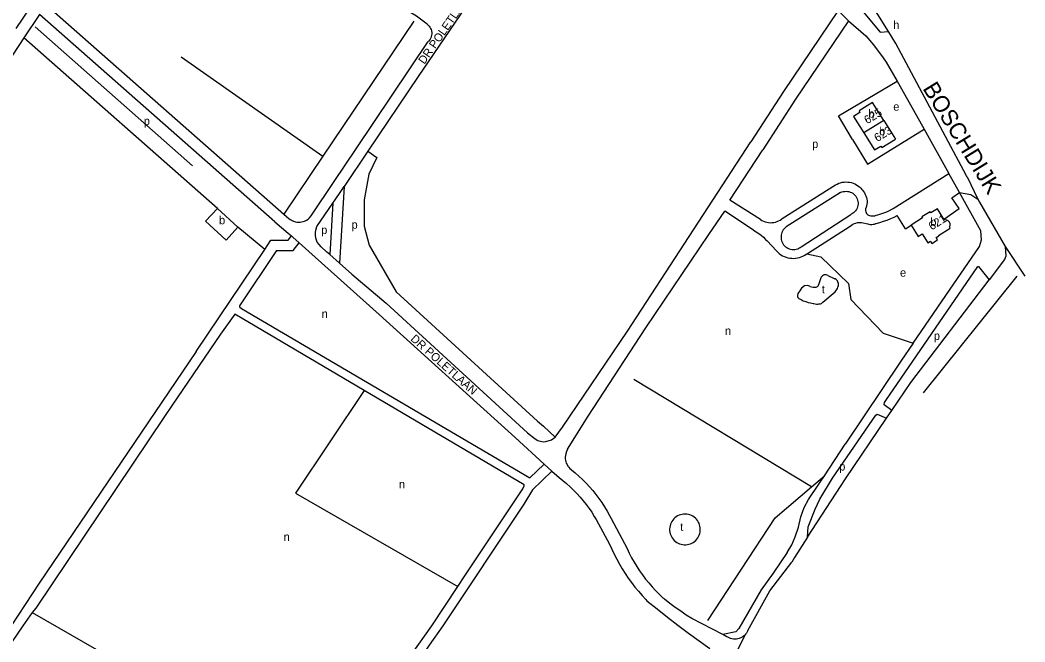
# Model space of a CAD drawing. Extents: x 158142 to 159655, y 385262 to 387204.
# Drawn here: x 159167.3 to 159654.9, y 385692.2 to 385994 of the extents above; entities that cross this region are included whole.
import ezdxf

# ---------------------------------------------------------------- set-up
doc = ezdxf.new("R2010")
doc.units = 0
for name, color, linetype in [('BLT_Basislijn', 7, 'Continuous'), ('BLT_Bebouwing', 7, 'Continuous'), ('BLT_Centroide', 7, 'Continuous'), ('BLT_Huisnummer', 7, 'Continuous'), ('BLT_Onderverdeling_panden', 7, 'Continuous'), ('BLT_Straatnaam_hoofdweg', 7, 'Continuous'), ('BLT_Straatnaam_verkleind', 7, 'Continuous'), ('BLT_Vlakafsluiter', 7, 'Continuous')]:
    doc.layers.add(name, color=color, linetype=linetype)

msp = doc.modelspace()

# ---------------------------------------------------------------- linework, layer by layer
at = {"layer": 'BLT_Basislijn'}
for p, q in [((159165.42, 385989.96), (159172.45, 386000.38)), ((159179.88, 386001.36), (159295.25, 385899.78)), ((159383.2, 386000), (159360.49, 385966.58)), ((159290.95, 385896.13), (159176.74, 385996.68)), ((159569.35, 385993.56), (159564.29, 385998.58)), ((159250.97, 385923.21), (159174.53, 385990.69)), ((159358.31, 385993.36), (159314.24, 385927.96)), ((159263.05, 385902.6), (159169.11, 385985.31)), ((159245.48, 385976.08), (159314.24, 385927.96)), ((159360.49, 385966.58), (159336.02, 385930.3)), ((159578.44, 385923.99), (159605.99, 385941.01)), ((159605.99, 385941.01), (159617.99, 385919.5)), ((159314.24, 385927.96), (159295.25, 385899.78)), ((159336.02, 385930.3), (159324.47, 385913.16)), ((159590.91, 385902.54), (159617.99, 385919.5)), ((159623.13, 385910.29), (159617.99, 385919.5)), ((159322.2, 385909.83), (159324.47, 385913.16)), ((159324.47, 385913.16), (159322.29, 385876.01)), ((159537.1, 385897.66), (159562.94, 385914)), ((159318.98, 385905.1), (159322.2, 385909.83)), ((159565.46, 385910.29), (159539.08, 385893.57)), ((159311.3, 385893.79), (159318.98, 385905.1)), ((159318.98, 385905.1), (159317.52, 385880.19)), ((159526.56, 385897.16), (159511.75, 385906.61)), ((159295.25, 385899.78), (159296.58, 385898.66)), ((159501.52, 385889.86), (159509.26, 385901.2)), ((159523.24, 385892.05), (159509.26, 385901.2)), ((159546.3, 385883.94), (159570.38, 385899.66)), ((159596.86, 385892.71), (159592.94, 385899.15)), ((159285.98, 385882.6), (159272.98, 385893.46)), ((159575.57, 385895.82), (159578.58, 385895.15)), ((159596.86, 385892.71), (159599.63, 385894.4)), ((159529.74, 385886.79), (159534.26, 385881.93)), ((159322.29, 385876.01), (159317.52, 385880.19)), ((159555.71, 385868.37), (159554.77, 385865.49)), ((159559.26, 385870.08), (159562.65, 385868.45)), ((159605.69, 385813.08), (159651.1, 385869.64)), ((159550.72, 385864.76), (159549.53, 385865.12)), ((159564.26, 385866.46), (159564.33, 385865.81)), ((159556.84, 385857.08), (159562.73, 385862.17)), ((159600.69, 385837.12), (159616.57, 385860.29)), ((159551.36, 385767.53), (159465.1, 385819.54)), ((159587.74, 385800.74), (159590.24, 385804.58)), ((159407.5, 385791.35), (159421.66, 385778.49)), ((159557.56, 385772.84), (159567.69, 385788.19)), ((159414.68, 385771.79), (159421.66, 385778.49)), ((159421.66, 385778.49), (159425.37, 385775.12)), ((159415.91, 385766.04), (159425.37, 385775.12)), ((159425.37, 385775.12), (159428.86, 385771.95)), ((159551.36, 385767.53), (159557.56, 385772.84)), ((159446.83, 385751.56), (159453.35, 385739.65)), ((159454.18, 385752.06), (159461.79, 385737.52)), ((159173.19, 385706.41), (159315.87, 385624.7)), ((159508.31, 385695.75), (159493.3, 385703.52)), ((159510.31, 385694.72), (159508.31, 385695.75))]:
    msp.add_line(p, q, dxfattribs=at)
for points in [[(159588.66, 385988.41), (159476.89, 386166.67), (159406.2, 386279.27)], [(159478.02, 386149.53), (159562.65, 386014.57), (159584.59, 385988.03), (159588.66, 385988.41)], [(159364.77, 385991.98), (159359.67, 385995.81), (159357.27, 385997.38), (159341.92, 386007.64), (159333.04, 386014.11), (159326.2, 386021.62)], [(159176.74, 385996.68), (159169.11, 385985.31)], [(159564.29, 385998.58), (159537.79, 385959.39), (159521.82, 385934.86)], [(159364.77, 385991.98), (159365.28, 385991.55), (159365.74, 385991.06), (159366.13, 385990.52), (159366.46, 385989.94), (159366.72, 385989.32), (159366.9, 385988.68), (159367, 385988.01), (159367.02, 385987.34), (159366.97, 385986.68), (159366.83, 385986.02), (159366.62, 385985.39), (159366.33, 385984.78), (159365.97, 385984.22), (159365.55, 385983.7), (159365.36, 385983.5)], [(159569.35, 385993.56), (159543.62, 385955.52), (159527.68, 385931.04)], [(159569.35, 385993.56), (159577.76, 385986.31), (159581.37, 385981.9), (159586.11, 385975.62)], [(159169.11, 385985.31), (159163.85, 385977.46), (159080.85, 385855.39)], [(159626.86, 385917.98), (159626.6, 385918.4), (159592.32, 385982.55), (159588.66, 385988.41)], [(159330.32, 385931.44), (159365.36, 385983.5)], [(159586.11, 385975.62), (159587.63, 385973.6), (159592.87, 385964.31)], [(159571.26, 385935.96), (159564.45, 385947.48), (159592.87, 385964.31)], [(159592.87, 385964.31), (159603.72, 385945.1), (159605.99, 385941.01)], [(159426.86, 385791.61), (159430.45, 385796.38), (159461.95, 385843.05), (159521.82, 385934.86)], [(159571.26, 385935.96), (159578.44, 385923.99)], [(159308.47, 385898.93), (159319.67, 385915.57), (159330.32, 385931.44)], [(159336.02, 385930.3), (159340.38, 385927.36), (159336.47, 385919.19), (159334.27, 385906.66), (159334.27, 385893.95), (159336.63, 385884.7), (159349.77, 385862.08), (159418.41, 385799.31), (159421.34, 385796.91), (159426.86, 385791.61)], [(159511.75, 385906.61), (159527.68, 385931.04)], [(159562.94, 385914), (159563.73, 385914.42), (159564.54, 385914.78), (159565.39, 385915.05), (159566.26, 385915.26), (159567.14, 385915.38), (159568.03, 385915.42), (159568.92, 385915.39), (159569.8, 385915.27), (159570.67, 385915.08), (159571.52, 385914.8), (159572.34, 385914.46), (159573.13, 385914.04), (159573.87, 385913.55), (159574.57, 385913), (159575.22, 385912.38), (159575.81, 385911.71), (159576.07, 385911.37)], [(159565.46, 385910.29), (159566.09, 385910.56), (159566.74, 385910.75), (159567.42, 385910.86), (159568.1, 385910.9), (159568.79, 385910.86), (159569.46, 385910.73), (159570.11, 385910.53), (159570.74, 385910.25), (159571.33, 385909.91), (159571.87, 385909.49), (159572.37, 385909.02), (159572.8, 385908.49), (159573.17, 385907.91), (159573.47, 385907.3), (159573.7, 385906.65), (159573.85, 385905.99), (159573.92, 385905.3), (159573.91, 385904.62), (159573.82, 385903.94), (159573.65, 385903.28), (159573.41, 385902.64), (159573.09, 385902.03), (159572.7, 385901.47), (159572.26, 385900.95), (159571.75, 385900.49), (159571.19, 385900.09), (159570.6, 385899.76), (159570.38, 385899.66)], [(159576.07, 385911.37), (159576.59, 385910.75), (159577.05, 385910.08), (159577.44, 385909.36), (159577.76, 385908.61), (159578, 385907.84), (159578.17, 385907.04), (159578.26, 385906.23), (159578.26, 385905.42), (159578.19, 385904.61), (159578.04, 385903.81), (159577.81, 385903.03), (159577.74, 385902.84)], [(159615.82, 385897.53), (159623, 385902.5), (159619.42, 385907.77), (159623.13, 385910.29)], [(159616.57, 385860.29), (159632.84, 385884.02), (159633.89, 385887.25), (159633.44, 385891.67), (159623.13, 385910.29)], [(159623.13, 385910.29), (159628.68, 385909.27), (159632, 385907.12)], [(159577.74, 385902.84), (159577.59, 385902.4), (159577.52, 385901.94), (159577.52, 385901.48), (159577.61, 385901.02), (159577.77, 385900.59), (159578.01, 385900.18), (159578.31, 385899.83), (159578.66, 385899.53), (159579.06, 385899.3), (159579.41, 385899.16)], [(159583.43, 385899.5), (159584.91, 385899.92), (159586.37, 385900.41), (159587.8, 385900.99), (159589.2, 385901.63), (159590.56, 385902.35), (159590.91, 385902.54)], [(159632, 385907.12), (159632.9, 385905.53), (159645.37, 385884.04)], [(159296.58, 385898.66), (159297.66, 385897.75), (159298.29, 385897.26), (159298.74, 385896.96), (159299.27, 385896.66), (159300, 385896.32), (159300.89, 385896.05), (159301.6, 385895.94), (159302.35, 385895.86), (159303.1, 385895.91), (159303.78, 385895.99), (159304.56, 385896.16), (159305.28, 385896.4), (159306.21, 385896.85), (159307, 385897.38), (159307.74, 385898.01), (159308.47, 385898.93)], [(159526.56, 385897.16), (159527.28, 385896.72), (159528.04, 385896.35), (159528.82, 385896.06), (159529.64, 385895.85), (159530.46, 385895.71), (159531.3, 385895.65), (159532.14, 385895.67), (159532.97, 385895.77), (159533.79, 385895.95), (159534.59, 385896.21), (159535.36, 385896.54), (159536.1, 385896.94), (159536.79, 385897.42), (159537.1, 385897.66)], [(159579.41, 385899.16), (159580.07, 385899.02), (159580.74, 385898.95), (159581.42, 385898.96), (159582.08, 385899.05), (159582.73, 385899.22), (159583.43, 385899.5)], [(159582.76, 385895.32), (159584.55, 385895.78), (159586.33, 385896.33), (159588.07, 385896.95), (159589.79, 385897.64), (159591.48, 385898.41), (159592.94, 385899.15)], [(159290.95, 385896.13), (159297.4, 385890.55)], [(159317.52, 385880.19), (159315.95, 385881.57), (159313.33, 385883.88), (159311.47, 385886.26), (159311.17, 385887.17), (159310.84, 385888.28), (159310.69, 385889.43), (159310.69, 385890.96), (159310.84, 385892.1), (159311.3, 385893.79)], [(159539.08, 385893.57), (159538.54, 385893.14), (159538.04, 385892.65), (159537.61, 385892.11), (159537.25, 385891.52), (159536.95, 385890.89), (159536.73, 385890.23), (159536.59, 385889.55), (159536.52, 385888.86), (159536.54, 385888.17), (159536.63, 385887.48), (159536.8, 385886.81), (159537.05, 385886.16), (159537.37, 385885.55), (159537.76, 385884.97), (159538.22, 385884.45), (159538.73, 385883.98), (159539.29, 385883.57), (159539.89, 385883.23), (159540.53, 385882.97), (159541.2, 385882.77), (159541.88, 385882.66), (159542.58, 385882.62), (159543.27, 385882.67), (159543.95, 385882.79), (159544.62, 385882.99), (159545.25, 385883.27), (159545.85, 385883.62), (159546.3, 385883.94)], [(159549.04, 385880.57), (159549.31, 385880.77), (159570.05, 385893.98)], [(159570.05, 385893.98), (159570.7, 385894.46), (159571.4, 385894.87), (159572.13, 385895.21), (159572.89, 385895.48), (159573.68, 385895.68), (159574.48, 385895.79), (159575.29, 385895.82), (159575.57, 385895.82)], [(159578.58, 385895.15), (159579.21, 385894.96), (159579.86, 385894.85), (159580.52, 385894.81), (159581.19, 385894.86), (159581.84, 385894.99), (159582.47, 385895.19), (159582.76, 385895.32)], [(159289.02, 385887.11), (159297.36, 385887.11), (159298.94, 385889.22)], [(159297.4, 385890.55), (159298.94, 385889.22)], [(159298.94, 385889.22), (159299.56, 385888.68), (159302.69, 385885.88)], [(159432.86, 385785.82), (159442.9, 385801.72), (159470.99, 385844.68), (159501.52, 385889.86)], [(159523.24, 385892.05), (159524.49, 385891.28), (159525.7, 385890.44), (159526.86, 385889.54), (159527.97, 385888.57), (159529.03, 385887.54), (159529.74, 385886.79)], [(159285.98, 385882.6), (159289.02, 385887.11)], [(159291.73, 385882.11), (159299.86, 385882.11), (159302.69, 385885.88)], [(159302.69, 385885.88), (159341.52, 385851.11)], [(159645.37, 385884.04), (159645.69, 385879.42), (159644.91, 385877.78), (159637.55, 385867.9)], [(159252.71, 385833.22), (159285.98, 385882.6)], [(159291.73, 385882.11), (159273.76, 385855.34), (159273.79, 385854.89), (159274.77, 385853.97), (159414.68, 385771.79)], [(159534.26, 385881.93), (159534.92, 385881.27), (159535.64, 385880.66), (159536.41, 385880.12), (159537.22, 385879.64), (159538.07, 385879.24), (159538.95, 385878.91), (159539.85, 385878.65), (159540.77, 385878.47), (159541.71, 385878.37), (159542.65, 385878.35), (159543.59, 385878.41), (159544.52, 385878.55), (159545.43, 385878.77), (159546.33, 385879.07), (159547.19, 385879.43), (159548.02, 385879.88), (159548.81, 385880.39), (159549.04, 385880.57)], [(159549.04, 385880.57), (159555.88, 385879.15), (159569.32, 385866.12), (159570.36, 385858.43), (159586.15, 385842.09), (159600.69, 385837.12)], [(159328.32, 385870.72), (159322.29, 385876.01)], [(159590.24, 385804.58), (159586.64, 385807.23), (159586.8, 385808.32), (159587.37, 385809.43), (159632.01, 385874.35), (159632.42, 385874.43), (159637.55, 385867.9)], [(159328.32, 385870.72), (159344.87, 385856.55), (159413.57, 385793.72), (159417.21, 385790.74), (159418.59, 385789.96), (159421.07, 385789.38), (159422.44, 385789.45), (159425.2, 385790.34), (159426.86, 385791.61)], [(159559.26, 385870.08), (159558.85, 385870.25), (159558.41, 385870.33), (159557.96, 385870.34), (159557.52, 385870.27), (159557.1, 385870.12), (159556.72, 385869.9), (159556.38, 385869.61), (159556.09, 385869.27), (159555.87, 385868.88), (159555.71, 385868.37)], [(159564.26, 385866.46), (159564.1, 385866.93), (159563.87, 385867.36), (159563.57, 385867.76), (159563.21, 385868.1), (159562.8, 385868.37), (159562.65, 385868.45)], [(159546.46, 385863.94), (159545.59, 385862.64), (159544.72, 385861.34), (159544.46, 385860.14)], [(159549.53, 385865.12), (159547.94, 385864.94), (159546.46, 385863.94)], [(159550.72, 385864.76), (159551.38, 385864.55), (159552.06, 385864.41), (159552.75, 385864.35), (159553.2, 385864.35)], [(159553.2, 385864.35), (159553.55, 385864.38), (159553.89, 385864.49), (159554.2, 385864.67), (159554.46, 385864.91), (159554.65, 385865.21), (159554.77, 385865.49)], [(159562.73, 385862.17), (159563.18, 385862.65), (159563.56, 385863.18), (159563.88, 385863.75), (159564.12, 385864.36), (159564.25, 385864.81)], [(159564.33, 385865.81), (159564.32, 385865.26), (159564.25, 385864.81)], [(159590.24, 385804.58), (159599.56, 385818.02), (159637.55, 385867.9)], [(159544.46, 385860.14), (159544.56, 385859.76), (159544.73, 385859.39), (159544.97, 385859.07), (159545.17, 385858.88)], [(159545.17, 385858.88), (159546.24, 385858.3), (159547.35, 385857.78), (159548.49, 385857.34), (159549.66, 385856.97), (159550.85, 385856.68), (159552.05, 385856.47), (159552.49, 385856.41)], [(159552.49, 385856.41), (159553.13, 385856.25), (159553.79, 385856.17), (159554.45, 385856.17), (159554.83, 385856.2)], [(159554.83, 385856.2), (159555.27, 385856.22), (159555.71, 385856.32), (159556.12, 385856.5), (159556.49, 385856.74), (159556.84, 385857.08)], [(159334.21, 385814.22), (159271.43, 385851.26), (159264.46, 385841.55), (159241.04, 385807.1), (159237.34, 385801.64), (159174.93, 385708.52), (159173.19, 385706.41)], [(159407.5, 385791.35), (159404.19, 385794.49), (159341.52, 385851.11)], [(159600.69, 385837.12), (159594.75, 385828.46), (159567.69, 385788.19)], [(159252.71, 385833.22), (159176.49, 385720.66), (159162.95, 385700), (159100, 385607.52), (159073.92, 385568.63)], [(159334.21, 385814.22), (159300.95, 385764.47), (159379.74, 385719.15)], [(159379.74, 385719.15), (159383.17, 385724.27), (159411.24, 385766.52), (159411.9, 385767.9), (159411.9, 385768.38), (159334.21, 385814.22)], [(159549.44, 385743.07), (159549.75, 385748.01), (159553.17, 385756.71), (159555.4, 385761.48), (159561.44, 385771.66), (159582.61, 385802.18), (159583.17, 385802.76), (159587.74, 385800.74)], [(159549.44, 385743.07), (159567.8, 385771.39), (159587.74, 385800.74)], [(159432.86, 385785.82), (159432.42, 385784.66), (159432.07, 385783.46), (159431.87, 385782.65)], [(159431.87, 385782.65), (159431.8, 385781.89), (159431.82, 385781.13), (159431.92, 385780.38), (159432.09, 385779.64), (159432.34, 385778.92), (159432.67, 385778.23), (159433.06, 385777.58), (159433.52, 385776.97), (159434.05, 385776.42), (159434.62, 385775.92), (159434.79, 385775.8)], [(159434.79, 385775.8), (159436.66, 385774.25), (159438.48, 385772.64), (159440.24, 385770.97), (159441.94, 385769.24), (159443.59, 385767.46), (159445.18, 385765.62), (159446.71, 385763.74), (159448.17, 385761.8), (159449.57, 385759.82), (159450.9, 385757.79), (159452.17, 385755.72), (159453.37, 385753.61), (159454.18, 385752.06)], [(159428.86, 385771.95), (159430.69, 385770.52), (159432.47, 385769.03), (159434.2, 385767.48), (159435.87, 385765.88), (159437.49, 385764.21), (159439.04, 385762.49), (159440.54, 385760.72), (159441.98, 385758.89), (159443.35, 385757.02), (159444.66, 385755.1), (159445.9, 385753.14), (159446.83, 385751.56)], [(159539.58, 385735.65), (159541.78, 385739.28), (159543.4, 385743.13), (159545.03, 385747.86), (159546.21, 385752.89), (159547.84, 385757.47), (159549.91, 385761.31), (159555.23, 385769.3), (159557.56, 385772.84)], [(159415.91, 385766.04), (159411.78, 385759.06), (159372.43, 385700), (159365.86, 385690.69), (159320.87, 385622.75)], [(159501.09, 385702.57), (159533.73, 385752.45), (159551.36, 385767.53)], [(159497.37, 385746.78), (159497.33, 385747.55), (159497.21, 385748.32), (159497.01, 385749.06), (159496.74, 385749.78), (159496.39, 385750.47), (159495.98, 385751.12), (159495.49, 385751.73), (159494.95, 385752.28), (159494.36, 385752.77), (159493.71, 385753.2), (159493.03, 385753.56), (159492.31, 385753.84), (159491.57, 385754.05), (159490.81, 385754.18), (159490.04, 385754.24), (159489.27, 385754.21), (159488.5, 385754.11), (159487.75, 385753.92), (159487.03, 385753.66), (159486.33, 385753.32), (159485.67, 385752.92), (159485.06, 385752.45), (159484.5, 385751.92), (159484, 385751.33), (159483.56, 385750.69), (159483.19, 385750.02), (159482.89, 385749.3), (159482.67, 385748.56), (159482.52, 385747.8), (159482.46, 385747.04), (159482.47, 385746.26), (159482.56, 385745.5), (159482.74, 385744.74), (159482.99, 385744.01), (159483.31, 385743.31), (159483.7, 385742.65), (159484.16, 385742.03), (159484.68, 385741.46), (159485.26, 385740.95), (159485.89, 385740.5), (159486.56, 385740.12), (159487.27, 385739.81), (159488.01, 385739.57), (159488.76, 385739.41), (159489.53, 385739.33), (159490.3, 385739.33), (159491.07, 385739.41), (159491.82, 385739.57), (159492.56, 385739.81), (159493.27, 385740.12), (159493.94, 385740.5), (159494.57, 385740.95), (159495.14, 385741.47), (159495.66, 385742.03), (159496.12, 385742.66), (159496.52, 385743.32), (159496.84, 385744.02), (159497.09, 385744.75), (159497.26, 385745.51), (159497.35, 385746.27), (159497.37, 385746.78)], [(159549.44, 385743.07), (159543.1, 385733.26), (159541.79, 385730.93)], [(159453.35, 385739.65), (159454.43, 385737.18), (159455.59, 385734.75), (159456.81, 385732.36), (159458.11, 385730), (159459.48, 385727.69), (159460.92, 385725.41), (159462.42, 385723.18), (159463.99, 385720.99), (159465.62, 385718.86), (159467.32, 385716.77), (159469.08, 385714.73), (159470.89, 385712.75), (159471.4, 385712.21)], [(159461.79, 385737.52), (159462.87, 385735.29), (159464.02, 385733.09), (159465.24, 385730.94), (159466.54, 385728.82), (159467.9, 385726.75), (159469.32, 385724.72), (159470.81, 385722.74), (159472.37, 385720.81), (159473.98, 385718.93), (159475.66, 385717.1), (159477.39, 385715.33), (159479.18, 385713.61), (159479.42, 385713.39)], [(159539.58, 385735.65), (159532.73, 385725.5), (159526.97, 385717.52), (159516.03, 385698.74), (159514.56, 385697.12), (159508.31, 385695.75)], [(159520.38, 385697.83), (159531.08, 385716.99), (159541.79, 385730.93)], [(159357.24, 385686.19), (159367.04, 385700), (159379.74, 385719.15)], [(159471.4, 385712.21), (159476.37, 385708.19), (159481.4, 385704.23), (159486.47, 385700.33), (159491.59, 385696.49), (159496.76, 385692.72), (159501.98, 385689.01)], [(159493.3, 385703.52), (159490.54, 385705.27), (159487.83, 385707.09), (159485.17, 385708.98), (159482.55, 385710.93), (159479.98, 385712.94), (159479.42, 385713.39)], [(159173.19, 385706.41), (159168.66, 385700), (159100, 385599.65), (159097.11, 385595.62), (159100, 385591.97), (159195.03, 385477.25), (159206.87, 385463.51), (159207.86, 385462.77), (159208.26, 385462.82), (159217.86, 385477.25)], [(159520.38, 385697.83), (159520.08, 385697.16), (159519.71, 385696.53), (159519.27, 385695.95)], [(159513.95, 385693.54), (159513.4, 385693.57), (159512.68, 385693.69), (159511.97, 385693.89), (159511.29, 385694.16), (159510.65, 385694.5), (159510.31, 385694.72)], [(159519.27, 385695.95), (159518.77, 385695.41), (159518.21, 385694.93), (159517.61, 385694.52), (159516.97, 385694.17), (159516.29, 385693.9), (159515.58, 385693.7), (159514.86, 385693.58), (159514.13, 385693.53), (159513.95, 385693.54)]]:
    msp.add_lwpolyline(points, dxfattribs=at)
at = {"layer": 'BLT_Bebouwing'}
for points in [[(159586.45, 385945.25), (159580.98, 385954.02), (159574.38, 385949.89), (159574.85, 385949.12), (159571.73, 385947.2), (159576.64, 385939.24)], [(159586.45, 385945.25), (159592.05, 385936.24)], [(159576.64, 385939.24), (159581.83, 385930.93), (159584.98, 385932.84), (159585.46, 385932.08), (159592.05, 385936.24)], [(159263.05, 385902.6), (159257.31, 385896.36), (159267.24, 385887.22), (159272.98, 385893.46)], [(159272.98, 385893.46), (159263.05, 385902.6)], [(159615.82, 385897.53), (159615.62, 385897.4), (159612.49, 385902.45), (159609.19, 385900.4), (159608.86, 385900.94), (159604.88, 385898.5), (159605.23, 385897.93), (159599.63, 385894.4)], [(159618.27, 385893.67), (159618.55, 385894.27), (159618.59, 385895.16), (159618.27, 385895.98), (159617.7, 385896.6), (159616.96, 385896.92), (159616.23, 385896.96), (159615.82, 385897.53)], [(159599.63, 385894.4), (159603.06, 385888.96), (159605.04, 385890.21), (159607.76, 385885.9), (159608.99, 385886.67), (159609.66, 385885.6), (159612.49, 385887.35), (159611.87, 385888.41), (159613.15, 385889.21), (159612.99, 385889.48), (159618.65, 385893.03), (159618.27, 385893.67)]]:
    msp.add_lwpolyline(points, dxfattribs=at)
at = {"layer": 'BLT_Onderverdeling_panden'}
msp.add_line((159586.45, 385945.25), (159576.64, 385939.24), dxfattribs=at)
at = {"layer": 'BLT_Vlakafsluiter'}
for p, q in [((159626.86, 385917.98), (159632, 385907.12)), ((159645.37, 385884.04), (159654.88, 385869.62)), ((159519.27, 385695.95), (159508.54, 385674.96))]:
    msp.add_line(p, q, dxfattribs=at)

# ---------------------------------------------------------------- texts
at = {"layer": 'BLT_Centroide'}
for s, p in [('h', (159590.96, 385989.65)), ('e', (159591, 385949.98)), ('b', (159578.84, 385946.62)), ('p', (159227.3, 385943)), ('b', (159584.13, 385938.09)), ('p', (159551.63, 385931.92)), ('b', (159263.82, 385894.91)), ('b', (159608.96, 385894.03)), ('p', (159313.39, 385890.16)), ('p', (159328.11, 385892.72)), ('e', (159594.26, 385869.46)), ('t', (159556.31, 385861.39)), ('n', (159313.63, 385849.47)), ('n', (159509.32, 385841.21)), ('p', (159610.7, 385838.77)), ('p', (159564.77, 385775.38)), ('n', (159351.1, 385766.75)), ('t', (159487.62, 385746.03)), ('n', (159295.19, 385741.24))]:
    msp.add_text(s, height=4, dxfattribs=at).set_placement(p)
at = {"layer": 'BLT_Huisnummer'}
for s, rotation, p in [('625', 31.4964, (159578.37, 385943.34)), ('623', 31.4964, (159583.24, 385934.71)), ('621', 32.2284, (159609.7, 385891.81))]:
    msp.add_text(s, height=4, rotation=rotation, dxfattribs=at).set_placement(p)
at = {"layer": 'BLT_Straatnaam_hoofdweg'}
msp.add_text('BOSCHDIJK', height=8, rotation=301.594, dxfattribs=at).set_placement((159605.04, 385960.81))
at = {"layer": 'BLT_Straatnaam_verkleind'}
for rotation, p in [(55.2331, (159363.45, 385972.25)), (318.407, (159356.46, 385838.81))]:
    msp.add_text('DR POLETLAAN', height=4, rotation=rotation, dxfattribs=at).set_placement(p)

doc.saveas('drawing.dxf')
